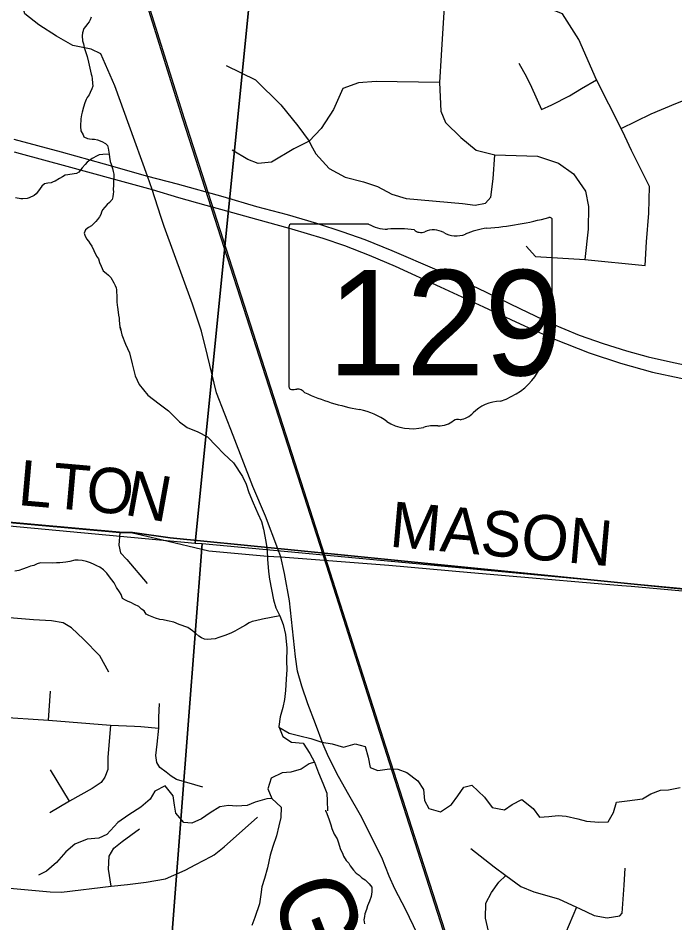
# Model space of a CAD drawing. Extents: x 0 to 34, y 0 to 22.
# Drawn here: x 7.633 to 8.456, y 19.591 to 20.723 of the extents above; entities that cross this region are included whole.
import ezdxf

# ---------------------------------------------------------------- set-up
doc = ezdxf.new("R2010")
doc.units = 0
for name, color, linetype in [('Default', 7, 'Continuous'), ('GM_X_Minor_River', 7, 'Continuous'), ('GM_X_Minor_River_Text', 7, 'Continuous'), ('GM_X_Rail_Line', 7, 'Continuous'), ('GM_X_Section', 7, 'Continuous'), ('GM_X_State_Location', 7, 'Continuous'), ('GM_X_State_Route', 7, 'Continuous'), ('GM_X_State_Shield', 7, 'Continuous'), ('GM_X_Township_Road', 7, 'Continuous'), ('GM_X_Township_Road_Text', 7, 'Continuous')]:
    doc.layers.add(name, color=color, linetype=linetype)

msp = doc.modelspace()

# ---------------------------------------------------------------- linework, layer by layer
at = {"layer": 'Default'}
for points in [[(7.9386, 20.9), (6.92, 20.9), (6.8487, 20.1601), (7.855, 20.0664)], [(8.9, 20.4078), (8.9, 20.9), (7.9386, 20.9), (7.855, 20.0664), (7.8637, 20.0659), (8.8506, 19.9738)]]:
    msp.add_lwpolyline(points, close=True, dxfattribs=at)
at = {"layer": 'GM_X_Minor_River'}
for points in [[(7.7246, 20.7243), (7.7237, 20.7212), (7.7222, 20.7186), (7.7202, 20.716), (7.7179, 20.713), (7.7156, 20.7104), (7.7139, 20.7047), (7.7135, 20.7013), (7.7141, 20.6948), (7.7152, 20.691), (7.7162, 20.6864), (7.7187, 20.6788), (7.7198, 20.6753), (7.7216, 20.6681), (7.7222, 20.6643), (7.7233, 20.6605), (7.724, 20.657), (7.7247, 20.6532), (7.7254, 20.6505), (7.7261, 20.6471), (7.7264, 20.6418), (7.7267, 20.6383), (7.7255, 20.6349), (7.7235, 20.63), (7.7223, 20.6274), (7.7199, 20.624), (7.7187, 20.6214), (7.7168, 20.6173), (7.7151, 20.612), (7.7135, 20.6056), (7.7127, 20.6022), (7.7118, 20.5972), (7.7118, 20.5942), (7.7113, 20.5908), (7.7116, 20.5877), (7.7119, 20.5824), (7.7148, 20.5774), (7.7156, 20.5747), (7.7201, 20.5727), (7.7227, 20.5723), (7.7261, 20.5719), (7.7288, 20.5718), (7.7329, 20.571), (7.7382, 20.569), (7.7427, 20.5662), (7.7453, 20.5639), (7.746, 20.5604), (7.7474, 20.5532), (7.7477, 20.5494), (7.7484, 20.544), (7.7498, 20.5406), (7.7516, 20.5352), (7.7523, 20.5314), (7.753, 20.528), (7.7527, 20.5143), (7.7522, 20.509), (7.7526, 20.506), (7.7525, 20.5033), (7.7521, 20.4995), (7.7512, 20.4961), (7.7477, 20.4924), (7.745, 20.4902), (7.7388, 20.4834), (7.7376, 20.4804), (7.7368, 20.4774), (7.7352, 20.4748), (7.7325, 20.4714), (7.7306, 20.4688), (7.7275, 20.4658), (7.7251, 20.4632), (7.7213, 20.4614), (7.7178, 20.4584), (7.7162, 20.4543), (7.7169, 20.4516), (7.7191, 20.447), (7.7214, 20.4443), (7.7236, 20.4408), (7.7258, 20.4381), (7.728, 20.4324)], [(7.7474, 20.5532), (7.7394, 20.5526), (7.7349, 20.5523), (7.7322, 20.5508), (7.726, 20.5475), (7.7199, 20.5431), (7.7172, 20.5401), (7.7137, 20.536), (7.7094, 20.5304), (7.7063, 20.5289), (7.7036, 20.5282), (7.6956, 20.5273), (7.6922, 20.5266), (7.6888, 20.5247), (7.6853, 20.5225), (7.6799, 20.5192), (7.6772, 20.5185), (7.6746, 20.517), (7.6704, 20.5167), (7.6662, 20.5157), (7.6631, 20.5131), (7.6588, 20.5071), (7.6561, 20.5034), (7.6534, 20.5011), (7.6472, 20.4982), (7.6445, 20.4975), (7.6392, 20.4972), (7.6366, 20.4973), (7.6301, 20.4982)], [(7.728, 20.4324), (7.7316, 20.4255), (7.7338, 20.422), (7.7353, 20.4174), (7.7374, 20.4128), (7.7385, 20.4101), (7.74, 20.407), (7.7434, 20.4043), (7.7463, 20.4016), (7.7493, 20.3985), (7.753, 20.392), (7.7548, 20.3885), (7.7559, 20.3858), (7.7566, 20.3831), (7.7566, 20.3805), (7.7569, 20.3763), (7.7568, 20.3733), (7.7571, 20.3683), (7.7574, 20.3641), (7.7577, 20.3615), (7.7587, 20.3554), (7.759, 20.3516), (7.7597, 20.3477), (7.7597, 20.3451), (7.7606, 20.3367), (7.7617, 20.3329)], [(7.7606, 20.3367), (7.7609, 20.3365), (7.7633, 20.3269), (7.7676, 20.3154), (7.7726, 20.3046), (7.7761, 20.2905), (7.7799, 20.2755), (7.7849, 20.2648), (7.7956, 20.2516), (7.8101, 20.2405), (7.8217, 20.2319), (7.8354, 20.2182), (7.8451, 20.2108), (7.8582, 20.2055), (7.8702, 20.1991), (7.8814, 20.1882), (7.891, 20.178), (7.9029, 20.1667), (7.9142, 20.1497), (7.9189, 20.1401), (7.9221, 20.1297), (7.9274, 20.1167), (7.9335, 20.1032), (7.9378, 20.0932), (7.9406, 20.0836), (7.9433, 20.0684), (7.9449, 20.0573), (7.9454, 20.0463), (7.9469, 20.0306), (7.9482, 20.0211), (7.9505, 20.0081), (7.9532, 19.9955), (7.956, 19.9852), (7.9611, 19.9752), (7.965, 19.9644), (7.9681, 19.9518), (7.9696, 19.935), (7.9695, 19.9187), (7.9696, 19.908), (7.969, 19.8959), (7.9682, 19.8818), (7.9668, 19.8705), (7.9647, 19.8606), (7.9613, 19.8489), (7.9595, 19.8368), (7.9645, 19.8242), (7.9757, 19.8174), (7.9901, 19.8159), (7.9985, 19.8031), (8.0043, 19.792), (8.0093, 19.7789), (8.0147, 19.7658), (8.0197, 19.7532), (8.0202, 19.7437), (8.0207, 19.7311)], [(7.9611, 19.9752), (7.9394, 19.9711), (7.9303, 19.9691), (7.9264, 19.9681), (7.9226, 19.9667), (7.9179, 19.9638), (7.9106, 19.9595), (7.9048, 19.9562), (7.8998, 19.9537), (7.8921, 19.9505), (7.8844, 19.9481), (7.8798, 19.9467), (7.8752, 19.9461), (7.8703, 19.9459), (7.8665, 19.946), (7.8627, 19.9476), (7.8594, 19.95), (7.856, 19.9532), (7.8516, 19.9567), (7.8456, 19.9607), (7.8351, 19.9644), (7.8283, 19.9673), (7.8204, 19.9691), (7.8151, 19.9704), (7.8106, 19.9709), (7.8053, 19.9726), (7.8012, 19.9742), (7.797, 19.9759), (7.7937, 19.9775), (7.7911, 19.9814), (7.7878, 19.9838), (7.7844, 19.9869), (7.7792, 19.9897), (7.7743, 19.9922), (7.771, 19.9934), (7.7676, 19.995), (7.7642, 19.997), (7.7625, 20.002), (7.7603, 20.0055), (7.7566, 20.0109), (7.7534, 20.0164), (7.7508, 20.0202), (7.7479, 20.0241), (7.7442, 20.0288), (7.7402, 20.0327), (7.7357, 20.0363), (7.732, 20.0379), (7.7286, 20.0395), (7.7241, 20.0416), (7.7188, 20.0433), (7.7135, 20.0446), (7.7086, 20.0451), (7.7044, 20.0448), (7.6979, 20.0431), (7.693, 20.0425), (7.6891, 20.0419), (7.6857, 20.0416), (7.6815, 20.0417), (7.6766, 20.0411), (7.6614, 20.0416), (7.6572, 20.0402), (7.6529, 20.0384), (7.6487, 20.0374), (7.6445, 20.0357), (7.6387, 20.0339), (7.6341, 20.0322), (7.6292, 20.0312)], [(7.9595, 19.8368), (7.9599, 19.8361), (7.9726, 19.8285), (7.9858, 19.8251), (7.9998, 19.8217), (8.0137, 19.8172), (8.0266, 19.815), (8.0405, 19.8108), (8.0551, 19.815), (8.0679, 19.8116), (8.0717, 19.7986), (8.0741, 19.7856), (8.0838, 19.7816), (8.0983, 19.7839), (8.1086, 19.7836), (8.1199, 19.7791), (8.1337, 19.7689), (8.1406, 19.7581), (8.1422, 19.7444), (8.1476, 19.7343), (8.1619, 19.7302), (8.1758, 19.7393), (8.1837, 19.7501), (8.1912, 19.761), (8.2011, 19.7634), (8.2171, 19.7485), (8.2266, 19.7354), (8.2421, 19.7327), (8.2518, 19.7393), (8.2641, 19.7454), (8.2779, 19.7344), (8.286, 19.7232), (8.2978, 19.724), (8.3092, 19.7253), (8.3194, 19.7246), (8.3338, 19.7212), (8.3447, 19.7183), (8.3603, 19.7171), (8.3721, 19.7176), (8.3788, 19.7292), (8.3825, 19.742), (8.3959, 19.744), (8.4149, 19.7465), (8.4254, 19.7527), (8.4376, 19.757), (8.4475, 19.7575), (8.462, 19.7605)], [(8.0043, 19.792), (7.9975, 19.7902), (7.9878, 19.7836), (7.9748, 19.7798), (7.9637, 19.7789), (7.9499, 19.7721), (7.9461, 19.7589), (7.9508, 19.7466), (7.9627, 19.736), (7.962, 19.7231), (7.9598, 19.7125), (7.9568, 19.7), (7.9523, 19.6868), (7.949, 19.6759), (7.9456, 19.66), (7.9418, 19.6468), (7.9385, 19.6363), (7.9371, 19.6264), (7.9353, 19.6151), (7.9296, 19.5977), (7.9259, 19.5879)], [(7.9508, 19.7466), (7.9447, 19.7463), (7.9301, 19.7422), (7.9202, 19.7378), (7.9068, 19.737), (7.8966, 19.7381), (7.8859, 19.7364), (7.8736, 19.7288), (7.8631, 19.7211), (7.8509, 19.716), (7.8406, 19.7167), (7.8307, 19.7283), (7.829, 19.7383), (7.8274, 19.7501), (7.8175, 19.7625), (7.8044, 19.756), (7.7988, 19.7459), (7.7868, 19.7359), (7.7721, 19.7264), (7.7582, 19.7165), (7.7445, 19.7017), (7.7345, 19.6973), (7.7197, 19.6958), (7.7043, 19.6894), (7.6931, 19.6798), (7.6814, 19.6668), (7.6689, 19.6557), (7.6589, 19.651)], [(8.018, 19.7322), (8.0181, 19.7318), (8.0199, 19.728), (8.0227, 19.7199), (8.0248, 19.7138), (8.0262, 19.7092), (8.029, 19.7019), (8.0327, 19.6964), (8.0341, 19.6926), (8.0368, 19.683), (8.0394, 19.6784), (8.0408, 19.6745), (8.044, 19.6691), (8.0474, 19.666), (8.0492, 19.6625), (8.0532, 19.657), (8.0565, 19.6531), (8.0602, 19.6507), (8.0635, 19.6476), (8.0676, 19.6448), (8.0728, 19.6401), (8.0761, 19.6358), (8.0763, 19.6301), (8.0754, 19.624), (8.0733, 19.6184), (8.0709, 19.6124), (8.0696, 19.6079), (8.0675, 19.6026), (8.0671, 19.5992), (8.0662, 19.5951), (8.0668, 19.5901)]]:
    msp.add_lwpolyline(points, dxfattribs=at)
at = {"layer": 'GM_X_Rail_Line'}
for points in [[(8.4398, 18.7255), (8.417, 18.7971), (8.3229, 19.0903), (8.2261, 19.3934), (8.0982, 19.7915), (8.0194, 20.0387), (7.8397, 20.5967), (7.7636, 20.8402), (7.7444, 20.9)], [(8.4419, 18.7255), (8.4189, 18.7977), (8.3247, 19.0909), (8.2279, 19.394), (8.1001, 19.7921), (8.0212, 20.0393), (7.8415, 20.5972), (7.7654, 20.8408), (7.7464, 20.9)]]:
    msp.add_lwpolyline(points, dxfattribs=at)
at = {"layer": 'GM_X_Section'}
for points in [[(6.8362, 20.1611), (6.8487, 20.1601), (7.855, 20.0664), (7.8637, 20.0659), (7.7938, 19.1583), (6.7522, 19.1603)], [(7.8637, 20.0659), (8.8506, 19.9738), (8.8752, 19.9725), (8.7834, 19.051), (7.7938, 19.1583)]]:
    msp.add_lwpolyline(points, close=True, dxfattribs=at)
at = {"layer": 'GM_X_State_Route'}
for points in [[(7.6278, 20.5719), (7.6871, 20.5558), (7.7412, 20.5408), (7.7951, 20.5256), (7.8323, 20.5157), (7.8897, 20.4999), (7.9318, 20.4875), (7.97, 20.4775), (8.0068, 20.4668), (8.0397, 20.4558), (8.0675, 20.4463), (8.1013, 20.4323), (8.1575, 20.4084), (8.208, 20.3856), (8.2615, 20.3597), (8.2998, 20.3416), (8.3357, 20.3265), (8.3656, 20.3161), (8.395, 20.3071), (8.4222, 20.2994), (8.4539, 20.2923), (8.476, 20.2878)], [(7.6283, 20.5559), (7.6361, 20.5538), (7.6945, 20.538), (7.7505, 20.5224), (7.8012, 20.5086), (7.8343, 20.4986), (7.8682, 20.4894)], [(7.8682, 20.4894), (7.8866, 20.4844), (7.9318, 20.4716), (7.9727, 20.4605)], [(7.9727, 20.4605), (7.9756, 20.4597), (8.0147, 20.4479), (8.042, 20.4387), (8.0726, 20.4268), (8.1055, 20.413), (8.1615, 20.387), (8.2159, 20.362), (8.2674, 20.3382), (8.3047, 20.3216), (8.3483, 20.3045), (8.3876, 20.2915), (8.4273, 20.2803), (8.463, 20.2729), (8.5077, 20.2655), (8.5599, 20.2604), (8.61, 20.2571), (8.6586, 20.254), (8.6956, 20.2515), (8.7632, 20.2476), (8.8472, 20.2411), (8.9, 20.2377)]]:
    msp.add_lwpolyline(points, dxfattribs=at)
at = {"layer": 'GM_X_State_Shield'}
for p, q in [((7.9724, 20.4622), (7.9724, 20.262)), ((8.0721, 20.4656), (7.9756, 20.4656)), ((8.302, 20.3659), (8.302, 20.4706)), ((8.3019, 20.3659), (8.302, 20.3659))]:
    msp.add_line(p, q, dxfattribs=at)
for centre, major_axis, start_param, end_param in [((8.1846, 20.7384), (0.3495, 0), 4.814394, 5.042369), ((8.2983, 20.471), (0.00367, 0), 6.141152, 7.989035), ((7.9762, 20.4626), (0.00382, 0), 1.712693, 3.28349), ((8.0951, 20.4888), (0.037, 0), 4.042523, 4.731795), ((8.1074, 20.3533), (0.133, 0), 1.404758, 1.657858), ((8.1533, 20.4405), (0.0222, 0), 0.950623, 2.079405), ((8.2291, 20.4045), (0.0703, 0), 1.699011, 2.107814), ((8.1376, 20.4636), (0.0107, 0), 3.836095, 5.185415), ((8.182, 20.4722), (0.0267, 0), 4.081561, 5.145723), ((8.3011, 20.3582), (0.00568, 0), 1.883978, 3.671073), ((8.2981, 20.3655), (0.00393, 0), 5.05454, 6.418171), ((8.265, 20.345), (0.0341, 0), 5.934695, 6.695948), ((8.3151, 20.3221), (0.0248, 0), 2.387724, 3.262537), ((8.2041, 20.3088), (0.0874, 0), 5.101752, 6.440018), ((7.9762, 20.2616), (0.00385, 0), 3.00124, 4.508301), ((7.9768, 20.2821), (0.0294, 0), 4.665946, 4.897461), ((7.9828, 20.2505), (0.0106, 0), 0.519207, 1.627899), ((8.1166, 20.4303), (0.2524, 0), 4.195997, 4.488961), ((8.0414, 20.1721), (0.079, 0), 0.823519, 1.323587), ((8.241, 20.2059), (0.0479, 0), 1.647645, 2.488434), ((8.1835, 20.2151), (0.00752, 0), 1.147584, 2.315152), ((8.1803, 20.2427), (0.0282, 0), 4.937069, 5.64225), ((8.1268, 20.2495), (0.0501, 0), 4.026481, 4.996735), ((8.1557, 20.1803), (0.0412, 0), 1.495662, 1.94098), ((8.1594, 20.2345), (0.0267, 0), 4.691044, 5.507374)]:
    msp.add_ellipse(centre, major_axis=major_axis, ratio=0.8, start_param=start_param, end_param=end_param, dxfattribs=at)
at = {"layer": 'GM_X_Township_Road'}
for p, q in [((8.3691, 20.0151), (8.389, 20.0134)), ((7.6712, 19.8448), (7.6739, 19.8812)), ((7.6975, 19.7433), (7.6737, 19.7826)), ((7.8558, 19.6642), (7.8748, 19.6743)), ((8.3323, 19.6107), (8.3141, 19.5672))]:
    msp.add_line(p, q, dxfattribs=at)
for points in [[(6.4945, 20.1803), (6.6784, 20.1674), (6.71, 20.1637), (6.7526, 20.1604), (6.7658, 20.1595), (6.8112, 20.1567), (6.8137, 20.1565), (6.8473, 20.1572), (6.8656, 20.1588), (6.8864, 20.1589), (6.9284, 20.155), (7.0596, 20.1449), (7.4148, 20.1115), (7.4871, 20.1047), (7.7604, 20.0801), (7.7765, 20.0797), (7.8238, 20.073), (7.9584, 20.0596), (8.6673, 19.9886), (8.7085, 19.9845), (8.8165, 19.9737), (8.9, 19.9667), (8.9, 20.9), (3.8479, 20.9)], [(7.7723, 20.5887), (7.7543, 20.6386), (7.7368, 20.6785), (7.7248, 20.6845), (7.702, 20.6889), (7.6815, 20.7006), (7.6591, 20.715), (7.6416, 20.7285), (7.6338, 20.756), (7.593, 20.9)], [(8.3928, 20.5754), (8.3882, 20.5851), (8.3574, 20.6459), (8.3352, 20.6964), (8.315, 20.7287), (8.2838, 20.7406), (8.1669, 20.7435), (8.0568, 20.7437), (8.0353, 20.7486), (8.0221, 20.7536), (8.013, 20.7588), (7.9967, 20.7799), (7.9795, 20.8184)], [(8.1666, 20.7375), (8.163, 20.677), (8.1607, 20.6427), (8.1625, 20.607), (8.1684, 20.5925), (8.1874, 20.574), (8.2068, 20.5581), (8.2299, 20.5523), (8.2837, 20.5505), (8.3099, 20.5419), (8.3284, 20.5283), (8.3438, 20.5066), (8.3474, 20.4876), (8.347, 20.4591), (8.3429, 20.4212)], [(7.8939, 20.6639), (7.9306, 20.6459), (7.9622, 20.6147), (7.9835, 20.5884), (7.9975, 20.5691), (7.9999, 20.5648)], [(8.2602, 20.6667), (8.2697, 20.6499), (8.2758, 20.6368), (8.2886, 20.6088), (8.3013, 20.6147), (8.3235, 20.626), (8.3384, 20.635), (8.3574, 20.6459)], [(8.1607, 20.6427), (8.0816, 20.644), (8.0594, 20.6422), (8.04, 20.635), (8.0281, 20.6091), (8.0125, 20.5851), (7.9975, 20.5691)], [(8.3882, 20.5851), (8.4259, 20.6034), (8.4568, 20.6165), (8.4843, 20.6273), (8.5018, 20.6268), (8.5591, 20.6099), (8.5876, 20.6036), (8.5974, 20.602)], [(7.8121, 20.475), (7.8012, 20.5086), (7.7951, 20.5256), (7.7723, 20.5887)], [(8.4184, 20.4135), (8.4198, 20.4433), (8.4229, 20.479), (8.4238, 20.5125), (8.4012, 20.5577), (8.3928, 20.5754)], [(7.9975, 20.5691), (7.9785, 20.5595), (7.9505, 20.5428), (7.9337, 20.5414), (7.9211, 20.5464), (7.9012, 20.5581)], [(7.9999, 20.5648), (8.0061, 20.5536), (8.0228, 20.5351), (8.0427, 20.5242), (8.0658, 20.5184), (8.0834, 20.5125), (8.101, 20.503), (8.1191, 20.4976), (8.1898, 20.4914), (8.2055, 20.4894), (8.2183, 20.4917), (8.2249, 20.4992), (8.2278, 20.5223), (8.2299, 20.5523)], [(7.9624, 20.049), (7.9586, 20.059), (7.9431, 20.1001), (7.927, 20.1373), (7.9026, 20.201), (7.8817, 20.2543), (7.8706, 20.301), (7.863, 20.3317), (7.8516, 20.3654), (7.8161, 20.4625), (7.8121, 20.475)], [(8.2692, 20.4379), (8.281, 20.4248), (8.3429, 20.4212), (8.4184, 20.4135)], [(8.9, 14.8595), (8.9, 19.9667), (8.8165, 19.9737), (8.7085, 19.9845), (8.6673, 19.9886), (7.9584, 20.0596), (7.8238, 20.073), (7.7765, 20.0797), (7.7604, 20.0801), (7.4871, 20.1047), (7.4148, 20.1115), (7.0596, 20.1449), (6.9284, 20.155), (6.8864, 20.1589), (6.8656, 20.1588), (6.8473, 20.1572), (6.8137, 20.1565), (6.8112, 20.1567), (6.7658, 20.1595), (6.7526, 20.1604), (6.71, 20.1637), (6.6784, 20.1674), (6.4945, 20.1803)], [(6.6776, 20.1669), (6.6786, 20.1669), (6.7103, 20.1631), (6.7528, 20.1599), (6.766, 20.159), (6.8114, 20.1561), (6.8139, 20.156), (6.8475, 20.1567), (6.8658, 20.1583), (6.8867, 20.1584), (6.9287, 20.1545), (7.0599, 20.1444), (7.415, 20.111), (7.4873, 20.1042), (7.7606, 20.0795), (7.7767, 20.0792), (7.8122, 20.071), (7.8722, 20.0568), (7.9457, 20.0501), (7.9615, 20.0491)], [(7.7606, 20.0795), (7.7592, 20.0638), (7.7613, 20.0543), (7.7694, 20.0459), (7.7948, 20.0157)], [(7.9615, 20.0491), (7.9624, 20.049), (8.0972, 20.0388), (8.2002, 20.0296)], [(8.2019, 19.3849), (8.1906, 19.4173), (8.1328, 19.5778), (8.1185, 19.6074), (8.1051, 19.6338), (8.0979, 19.6497), (8.0885, 19.673), (8.0618, 19.7259), (8.0472, 19.7513), (8.0345, 19.7741), (8.0218, 19.7987), (8.0153, 19.8143), (8.0057, 19.8401), (7.996, 19.8652), (7.9885, 19.8873), (7.9832, 19.9061), (7.9805, 19.9239), (7.9729, 19.994), (7.9667, 20.0283), (7.9624, 20.049)], [(8.2002, 20.0296), (8.2625, 20.0241), (8.3691, 20.0151)], [(8.389, 20.0134), (8.4009, 20.0124), (8.5382, 19.9999)], [(7.747, 19.905), (7.7355, 19.9251), (7.7151, 19.9462), (7.7001, 19.9601), (7.6898, 19.9666), (7.6753, 19.9691), (7.6527, 19.9704), (7.6125, 19.9735), (7.5916, 19.9769)], [(7.8645, 19.7611), (7.8315, 19.7705), (7.8249, 19.7747), (7.8185, 19.7796), (7.8108, 19.7856), (7.807, 19.7919), (7.8059, 19.8004), (7.8072, 19.8148), (7.8094, 19.8347), (7.8094, 19.8482), (7.8103, 19.8656)], [(7.607, 19.8489), (7.6712, 19.8448), (7.749, 19.8386), (7.7791, 19.8371)], [(7.749, 19.8386), (7.7458, 19.798), (7.7455, 19.7831), (7.7417, 19.7733), (7.7373, 19.7666), (7.7262, 19.7592), (7.6975, 19.7433), (7.6731, 19.7287)], [(7.7791, 19.8371), (7.7871, 19.8367), (7.8094, 19.8347)], [(7.8748, 19.6743), (7.8786, 19.6764), (7.8914, 19.6864), (7.9331, 19.7232)], [(7.7497, 19.637), (7.7464, 19.6585), (7.7475, 19.6746), (7.753, 19.6846), (7.7637, 19.6931), (7.7851, 19.7088)], [(8.2001, 19.6843), (8.2293, 19.6613), (8.2439, 19.6505), (8.2628, 19.6367), (8.2788, 19.6299), (8.3099, 19.621), (8.3323, 19.6107), (8.3361, 19.6089), (8.3545, 19.6002), (8.3707, 19.5974), (8.3865, 19.6001), (8.3893, 19.6034), (8.392, 19.6384), (8.3931, 19.6595)], [(7.449, 19.6509), (7.595, 19.6372), (7.6735, 19.6301), (7.6875, 19.6297), (7.7497, 19.637), (7.7702, 19.639), (7.7938, 19.6421), (7.8178, 19.6463), (7.8426, 19.6571), (7.8558, 19.6642)], [(8.2969, 19.4257), (8.2919, 19.4405), (8.2769, 19.4607), (8.2716, 19.4687), (8.267, 19.4822), (8.2672, 19.4989), (8.2658, 19.5139), (8.2574, 19.5249), (8.2469, 19.5339), (8.2378, 19.542), (8.2297, 19.5504), (8.2241, 19.5714), (8.2185, 19.597), (8.2188, 19.6159), (8.2259, 19.6293), (8.2353, 19.6419), (8.2439, 19.6505)]]:
    msp.add_lwpolyline(points, dxfattribs=at)

# ---------------------------------------------------------------- texts
at = {"layer": 'GM_X_Minor_River_Text'}
msp.add_text('Gregory', height=0.09469, rotation=291.3879, dxfattribs=at).set_placement((7.9475, 19.6299))
at = {"layer": 'GM_X_State_Location'}
for s in ['s', 'r']:
    msp.add_text(s, height=0.000189, dxfattribs=at).set_placement((8.1335, 20.3488))
msp.add_text('129', height=0.000189, rotation=0, dxfattribs=at).set_placement((8.0666, 20.335))
at = {"layer": 'GM_X_State_Shield'}
msp.add_text('129', height=0.13184, dxfattribs=at).set_placement((8.0209, 20.2762))
at = {"layer": 'GM_X_Township_Road_Text'}
for s, height, rotation, p in [('L', 0.0568, 354.962, (7.632, 20.1141)), ('T', 0.0568, 354.964, (7.6744, 20.1104)), ('O', 0.0568, 354.6263, (7.7166, 20.1066)), ('N', 0.0568, 349.716, (7.7651, 20.1021)), ('MASON', 0.05682, 354.9079, (8.0972, 20.062))]:
    msp.add_text(s, height=height, rotation=rotation, dxfattribs=at).set_placement(p)

doc.saveas('drawing.dxf')
